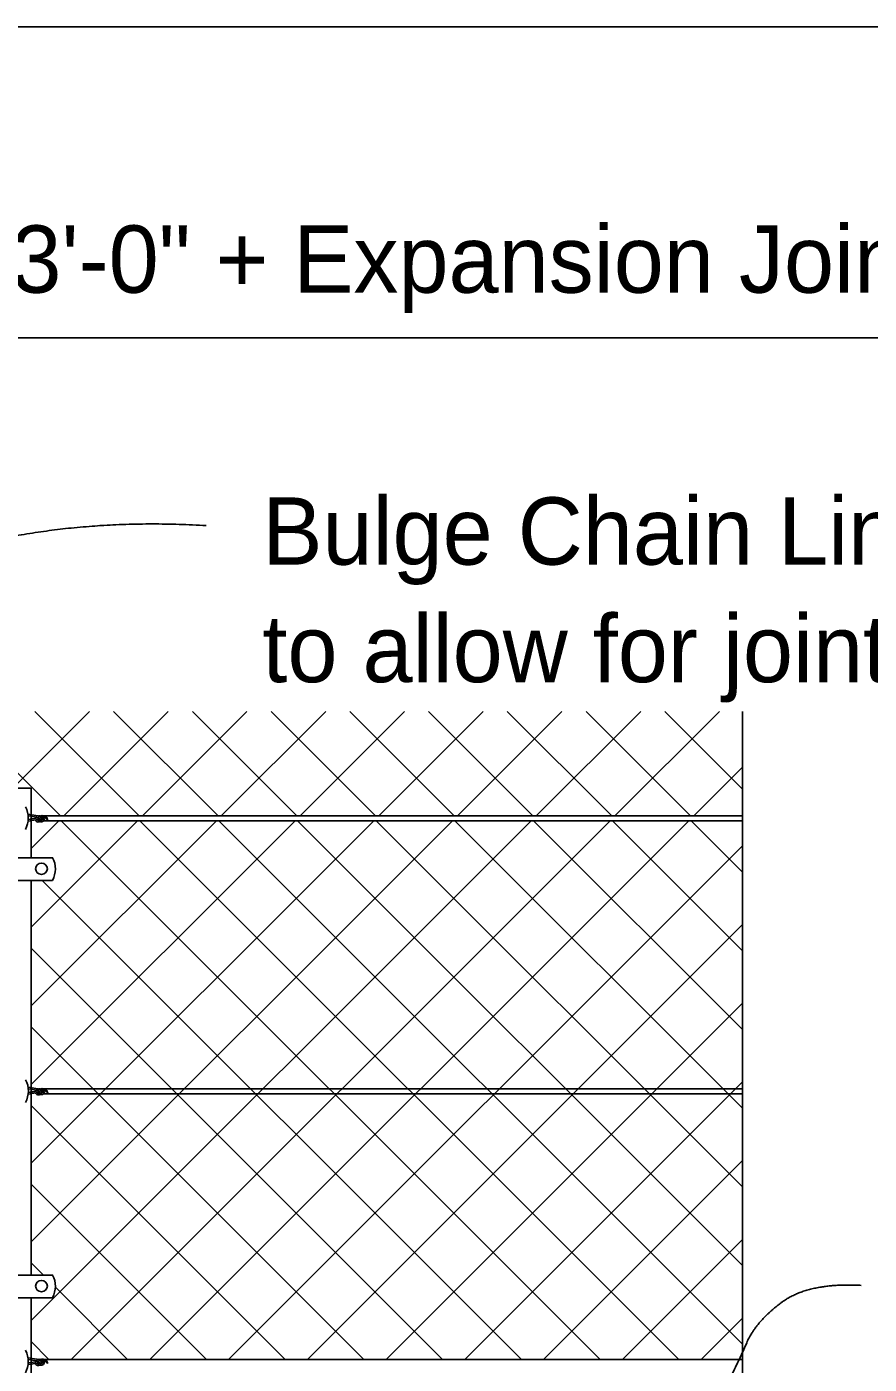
# Model space of a CAD drawing. Extents: x 0 to 41.1, y 0 to 26.4.
# Drawn here: x 28.834 to 31.356, y 22.394 to 26.4 of the extents above; entities that cross this region are included whole.
import ezdxf

# ---------------------------------------------------------------- set-up
doc = ezdxf.new("R2010")
doc.units = 0
for name, color, linetype in [('Dimension', 7, 'Continuous'), ('Miscellaneous', 7, 'Continuous'), ('Miscellaneous1', 7, 'Continuous'), ('SteelMisc', 7, 'Continuous'), ('TextStructures', 7, 'Continuous')]:
    doc.layers.add(name, color=color, linetype=linetype)

msp = doc.modelspace()

# ---------------------------------------------------------------- linework, layer by layer
at = {"layer": 'Dimension'}
msp.add_line((25.6609, 25.4682), (35.6727, 25.4682), dxfattribs=at)
msp.add_lwpolyline([(30.9762, 24.349), (30.9762, 21.1819), (31.0795, 21.1819), (30.9762, 21.1369), (30.8729, 21.0919), (30.9762, 21.0919), (30.9762, 20.1983)], dxfattribs=at)
for points in [[(29.3712, 24.906), (28.9427, 24.9313), (28.2117, 24.7126), (27.9092, 24.1238), (27.7412, 22.6169)], [(31.3313, 22.6303), (31.1747, 22.6384), (31.0168, 22.5231), (30.9598, 22.3905), (30.866, 22.2085), (30.5227, 21.5216)]]:
    msp.add_open_spline(points, degree=2, dxfattribs=at)
at = {"layer": 'Miscellaneous'}
for p, q in [((28.7357, 24.0631), (29.0217, 24.349)), ((28.8582, 24.349), (29.1707, 24.0365)), ((28.9448, 24.0365), (29.2574, 24.349)), ((29.0939, 24.349), (29.4064, 24.0365)), ((29.1805, 24.0365), (29.4931, 24.349)), ((29.3296, 24.349), (29.6421, 24.0365)), ((29.4162, 24.0365), (29.7288, 24.349)), ((29.5653, 24.349), (29.8778, 24.0365)), ((29.6519, 24.0365), (29.9645, 24.349)), ((29.801, 24.349), (30.1135, 24.0365)), ((29.8876, 24.0365), (30.2002, 24.349)), ((30.0367, 24.349), (30.3492, 24.0365)), ((30.1233, 24.0365), (30.4359, 24.349)), ((30.2724, 24.349), (30.5849, 24.0365)), ((30.359, 24.0365), (30.6716, 24.349)), ((30.5081, 24.349), (30.8206, 24.0365)), ((30.5947, 24.0365), (30.9073, 24.349)), ((30.7438, 24.349), (30.9762, 24.1166)), ((28.7221, 24.2494), (28.935, 24.0365)), ((30.8304, 24.0365), (30.9762, 24.1823)), ((28.8471, 22.5246), (30.3443, 24.0218)), ((28.8471, 22.7603), (30.1086, 24.0218)), ((28.8471, 22.996), (29.8729, 24.0218)), ((28.8471, 23.2317), (29.6372, 24.0218)), ((28.8471, 23.4674), (29.4015, 24.0218)), ((28.8471, 23.7031), (29.1658, 24.0218)), ((28.8471, 23.9388), (28.9301, 24.0218)), ((28.937, 24.0218), (30.5501, 22.4086)), ((28.9669, 22.4086), (30.58, 24.0218)), ((29.1727, 24.0218), (30.7858, 22.4086)), ((29.2026, 22.4086), (30.8157, 24.0218)), ((29.4084, 24.0218), (30.9762, 22.4539)), ((29.6441, 24.0218), (30.9762, 22.6896)), ((29.8798, 24.0218), (30.9762, 22.9253)), ((30.1155, 24.0218), (30.9762, 23.161)), ((30.3512, 24.0218), (30.9762, 23.3967)), ((30.5869, 24.0218), (30.9762, 23.6324)), ((30.8226, 24.0218), (30.9762, 23.8681)), ((29.4383, 22.4086), (30.9762, 23.9466)), ((28.8797, 23.8433), (30.3144, 22.4086)), ((29.674, 22.4086), (30.9762, 23.7109)), ((28.8471, 23.6402), (30.0787, 22.4086)), ((29.9097, 22.4086), (30.9762, 23.4752)), ((28.8471, 23.4045), (29.843, 22.4086)), ((30.1454, 22.4086), (30.9762, 23.2395)), ((28.8471, 23.1688), (29.6073, 22.4086)), ((30.3811, 22.4086), (30.9762, 23.0038)), ((28.8471, 22.9331), (29.3716, 22.4086)), ((30.6168, 22.4086), (30.9762, 22.768)), ((28.8471, 22.6974), (28.8836, 22.6609)), ((28.9196, 22.6249), (29.1359, 22.4086)), ((30.8525, 22.4086), (30.9762, 22.5323)), ((28.8471, 22.4617), (28.9002, 22.4086))]:
    msp.add_line(p, q, dxfattribs=at)
at = {"layer": 'Miscellaneous1'}
msp.add_lwpolyline([(0, 26.4), (41.0667, 26.4), (41.0667, 0), (0, 0)], close=True, dxfattribs=at)
at = {"layer": 'SteelMisc'}
for p, q in [((28.7846, 24.1198), (28.8471, 24.1198)), ((28.8471, 24.0396), (28.8471, 24.1198)), ((28.8375, 24.0412), (28.8668, 24.0366)), ((28.8376, 24.0412), (28.8669, 24.0366)), ((28.8471, 24.0636), (28.8471, 23.9109)), ((28.8855, 24.0365), (30.9761, 24.0365)), ((28.838, 24.0207), (28.8717, 24.0264)), ((28.8381, 24.0362), (28.8642, 24.0321)), ((28.8381, 24.0207), (28.8718, 24.0264)), ((28.8382, 24.0362), (28.8643, 24.0321)), ((28.8384, 24.0255), (28.8683, 24.0304)), ((28.8385, 24.0255), (28.8684, 24.0304)), ((28.8471, 24.0347), (28.8471, 24.0269)), ((28.8841, 24.0218), (30.9761, 24.0218)), ((28.4206, 23.9109), (28.9116, 23.9109)), ((28.4206, 23.8433), (28.9109, 23.8433)), ((28.8471, 23.8433), (28.8471, 22.6609)), ((28.8377, 23.2237), (28.8669, 23.2191)), ((28.8378, 23.2237), (28.8671, 23.2191)), ((28.8382, 23.2033), (28.8718, 23.2089)), ((28.8383, 23.2187), (28.8643, 23.2146)), ((28.8383, 23.2033), (28.8719, 23.2089)), ((28.8384, 23.2187), (28.8644, 23.2146)), ((28.8386, 23.2081), (28.8685, 23.213)), ((28.8387, 23.2081), (28.8686, 23.213)), ((28.8472, 23.2172), (28.8472, 23.2094)), ((28.8843, 23.2043), (30.9763, 23.2043)), ((28.8856, 23.219), (30.9763, 23.219)), ((28.8471, 22.9552), (28.8471, 22.7653)), ((28.4206, 22.6609), (28.9116, 22.6609)), ((28.4206, 22.5933), (28.9109, 22.5933)), ((28.8471, 21.4109), (28.8471, 22.5933)), ((28.8376, 22.4133), (28.8642, 22.4089)), ((28.8381, 22.3929), (28.8719, 22.3985)), ((28.8382, 22.4083), (28.8641, 22.4041)), ((28.8385, 22.3977), (28.8687, 22.4026)), ((28.8471, 22.4069), (28.8471, 22.399)), ((28.8854, 22.4086), (30.9761, 22.4086))]:
    msp.add_line(p, q, dxfattribs=at)
for centre, major_axis, ratio, start_param, end_param in [((28.7609, 24.03), (0.0776, 0), 0.957868, 5.803915, 6.752041), ((28.8654, 24.0274), (0.0115, -0.0041), 0.737732, 5.08821, 8.212701), ((28.871, 24.0283), (-0.00872, 0), 0.957868, 2.1008, 4.992926), ((28.8776, 24.0288), (-0.00872, 0), 0.957868, 3.323334, 4.992926), ((28.8823, 24.0233), (-0.0142, 0), 0.957868, 3.141593, 4.79635), ((28.8693, 24.0267), (-0.0095, 0), 0.957868, 5.673972, 6.052579), ((28.8693, 24.0267), (-0.0095, 0), 0.957868, 0.252467, 1.271421), ((28.8634, 24.0225), (0.00982, 0), 0.957868, 0.655696, 1.505671), ((28.8688, 24.025), (0.00301, 0), 0.957868, 3.28349, 5.170635), ((28.8694, 24.0272), (-0.00453, 0), 0.957868, 5.149727, 5.551998), ((28.8666, 24.0259), (0.00527, 0), 0.957868, 5.058829, 7.342751), ((28.8688, 24.025), (0.00301, 0), 0.957868, 0.004594, 0.141897), ((28.8771, 24.0278), (0.00944, 0), 0.957868, 4.316497, 6.557353), ((28.8776, 24.0288), (-0.00503, 0), 0.92697, 1.780895, 4.712389), ((28.8743, 24.0082), (0.0274, 0), 0.957868, 0.628521, 1.149654), ((28.842, 23.8778), (0.0776, 0), 0.957868, 5.801244, 6.745158), ((28.7611, 23.2125), (0.0776, 0), 0.957868, 5.803915, 6.752041), ((28.8695, 23.2092), (-0.0095, 0), 0.957868, 5.673972, 6.052579), ((28.8695, 23.2092), (-0.0095, 0), 0.957868, 0.252467, 1.271421), ((28.8655, 23.2099), (0.0115, -0.0041), 0.737732, 5.08821, 8.212701), ((28.8636, 23.205), (0.00982, 0), 0.957868, 0.655696, 1.505671), ((28.8689, 23.2075), (0.00301, 0), 0.957868, 3.28349, 5.170635), ((28.8696, 23.2097), (-0.00453, 0), 0.957868, 5.149727, 5.551998), ((28.8668, 23.2084), (0.00527, 0), 0.957868, 5.058829, 7.342751), ((28.8712, 23.2108), (-0.00872, 0), 0.957868, 2.1008, 4.992926), ((28.8689, 23.2075), (0.00301, 0), 0.957868, 0.004594, 0.141897), ((28.8773, 23.2104), (0.00944, 0), 0.957868, 4.316497, 6.557353), ((28.8777, 23.2113), (-0.00872, 0), 0.957868, 3.323334, 4.992926), ((28.8777, 23.2113), (-0.00503, 0), 0.92697, 1.780895, 4.712389), ((28.8825, 23.2058), (-0.0142, 0), 0.957868, 3.141593, 4.79635), ((28.8745, 23.1908), (0.0274, 0), 0.957868, 0.628521, 1.149654), ((28.842, 22.6278), (0.0776, 0), 0.957868, 5.801244, 6.745158), ((28.7609, 22.4022), (0.0776, 0), 0.957868, 5.803915, 6.752041), ((28.8693, 22.3989), (-0.0095, 0), 0.957868, 5.62303, 6.01932), ((28.8693, 22.3989), (-0.0095, 0), 0.957868, 0.252467, 1.247174), ((28.8634, 22.3947), (0.00982, 0), 0.957868, 0.636815, 1.505671), ((28.8654, 22.3996), (0.0115, -0.0041), 0.737732, 5.048267, 8.212701), ((28.8688, 22.3971), (0.00301, 0), 0.957868, 3.003465, 5.497792), ((28.8694, 22.3993), (-0.00453, 0), 0.957868, 5.149727, 5.551998), ((28.871, 22.4004), (-0.00872, 0), 0.957868, 2.114937, 5.0803), ((28.8666, 22.398), (0.00527, 0), 0.957868, 5.660961, 6.743457), ((28.8688, 22.3971), (0.00301, 0), 0.957868, 0.004594, 0.483719), ((28.8771, 22.4), (0.00944, 0), 0.957868, 4.319295, 6.652508), ((28.8776, 22.4009), (-0.00872, 0), 0.957868, 3.422117, 5.180096), ((28.8776, 22.4009), (-0.00503, 0), 0.92697, 1.789502, 4.651061), ((28.8823, 22.3954), (-0.0142, 0), 0.957868, 3.175145, 4.85532), ((28.8743, 22.3804), (0.0274, 0), 0.957868, 0.63108, 1.149654)]:
    msp.add_ellipse(centre, major_axis=major_axis, ratio=ratio, start_param=start_param, end_param=end_param, dxfattribs=at)
for centre in [(28.8779, 23.8782), (28.8779, 22.6282)]:
    msp.add_ellipse(centre, major_axis=(-0.0177, 0), ratio=0.957868, dxfattribs=at)

# ---------------------------------------------------------------- texts
at = {"layer": 'Dimension'}
for s, p in [('Bulge Chain Link Fabric', (29.5393, 24.7888)), ('to allow for joint movement', (29.5393, 24.4368))]:
    msp.add_text(s, height=0.2016, dxfattribs=at).set_placement(p)
at = {"layer": 'TextStructures'}
msp.add_text('3\'-0" + Expansion Joint Opening (See Note 2)', height=0.2016, dxfattribs=at).set_placement((28.7879, 25.6033))

doc.saveas('drawing.dxf')
